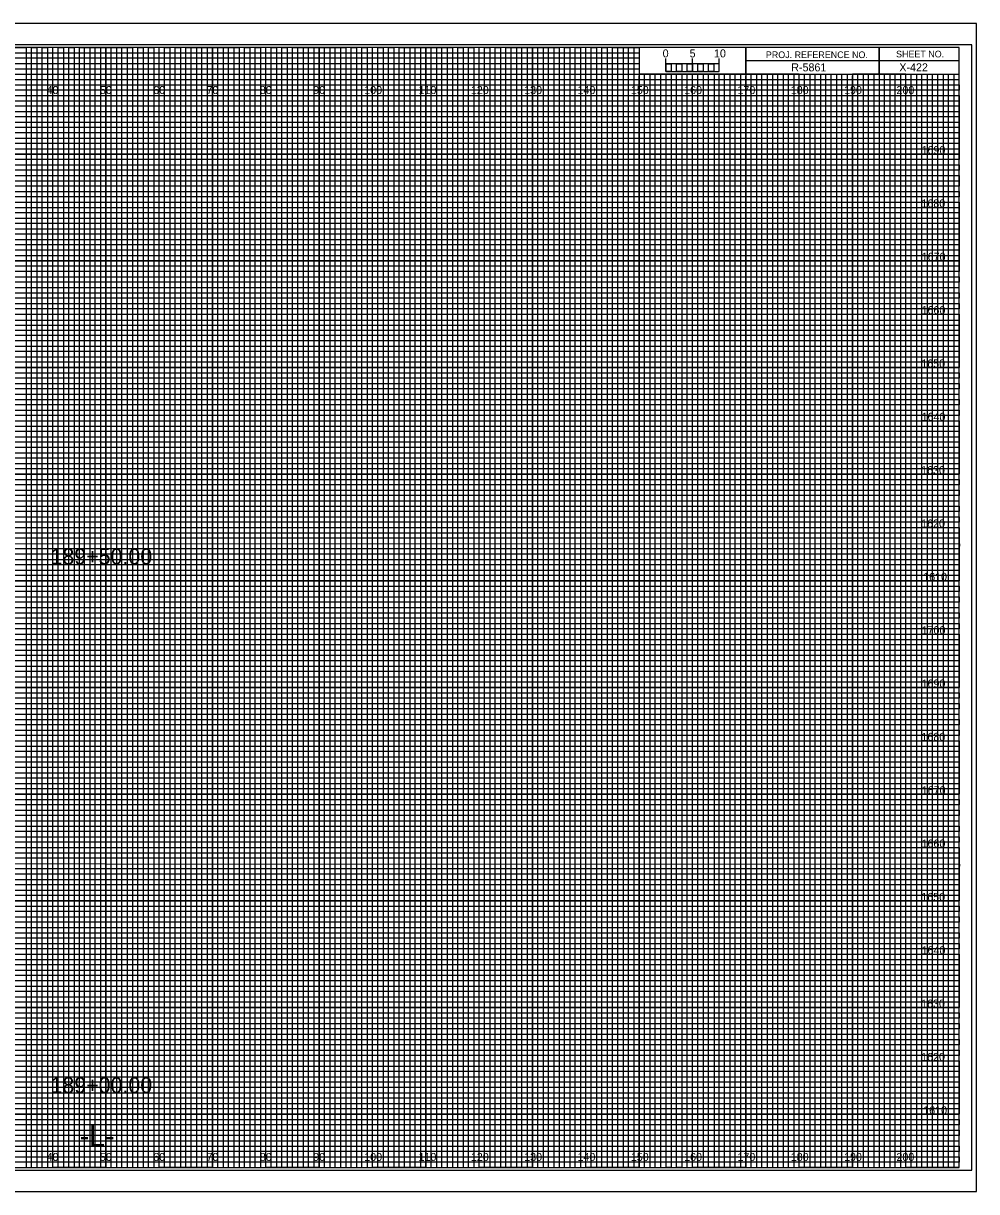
# Model space of a CAD drawing. Extents: x -13 to 323, y -5 to 6154.
# Drawn here: x 144.5 to 323.3, y 3955.5 to 4174.5 of the extents above; entities that cross this region are included whole.
import ezdxf

# ---------------------------------------------------------------- set-up
doc = ezdxf.new("R2010")
doc.units = 0
for name, color, linetype in [('Exist CMT Ground Line', 7, 'Continuous'), ('Prop Horizontal Alignment', 7, 'Continuous'), ('Prop Retaining Wall', 7, 'Continuous'), ('Prop XS Alignment Label', 7, 'Continuous'), ('Prop XS Bar Scale Labels', 7, 'Continuous'), ('Prop XS DDE', 7, 'Continuous'), ('Prop XS DDE Elevations', 7, 'Continuous'), ('Prop XS DDE Slope Text', 7, 'Continuous'), ('Prop XS Earthwork Shape', 7, 'Continuous'), ('Prop XS Elevation Labels', 7, 'Continuous'), ('Prop XS Project Number', 7, 'Continuous'), ('Prop XS Sheet Number', 7, 'Continuous'), ('Prop XS Station Labels', 7, 'Continuous'), ('Raster_Level_0', 7, 'Continuous'), ('Scratch_Level_3', 7, 'Continuous'), ('Sheet Cutting Line CELL', 7, 'Continuous')]:
    doc.layers.add(name, color=color, linetype=linetype)

msp = doc.modelspace()

# ---------------------------------------------------------------- linework, layer by layer
at = {"layer": 'Exist CMT Ground Line'}
for p, q in [((265, 4165.49), (265, 4167.9)), ((265, 4166.9), (265, 4167.9)), ((270, 4165.49), (270, 4167.9)), ((275, 4165.49), (275, 4167.9)), ((275, 4166.9), (275, 4167.9))]:
    msp.add_line(p, q, dxfattribs=at)
for points in [[(275, 4166.9), (265, 4166.9), (265, 4165.49), (275, 4165.49)], [(265, 4166.9), (266, 4166.9), (266, 4165.49), (265, 4165.49)], [(267, 4166.9), (268, 4166.9), (268, 4165.49), (267, 4165.49)], [(269, 4166.9), (270, 4166.9), (270, 4165.49), (269, 4165.49)], [(271, 4166.9), (272, 4166.9), (272, 4165.49), (271, 4165.49)], [(273, 4166.9), (274, 4166.9), (274, 4165.49), (273, 4165.49)]]:
    msp.add_lwpolyline(points, close=True, dxfattribs=at)
at = {"layer": 'Prop Retaining Wall'}
for p, q in [((0, 4169), (260, 4169)), ((260, 4167.98), (0, 4167.98)), ((260, 4169), (260, 4167.98)), ((0, 4167), (260, 4167)), ((260, 4165.89), (0, 4165.89)), ((260, 4167), (260, 4165.89)), ((0, 4164), (320, 4164))]:
    msp.add_line(p, q, dxfattribs=at)
for points in [[(0, 4163), (270, 4163), (320, 4163), (320, 4162), (0, 4162)], [(0, 4161), (320, 4161), (320, 4159), (0, 4159)], [(0, 4158), (320, 4158), (320, 4157), (0, 4156.98)], [(0, 4156), (320, 4156), (320, 4154), (0, 4154)], [(0, 4153), (320, 4153), (320, 4152), (0, 4152)], [(0, 4151), (320, 4151), (320, 4149), (0, 4149)], [(0, 4148), (320, 4148), (320, 4147), (0, 4147)], [(0, 4146), (320, 4146), (320, 4144), (0, 4144)], [(0, 4143), (320, 4143), (320, 4142), (0, 4142)], [(0, 4141), (320, 4141), (320, 4139), (0, 4139)], [(0, 4138), (320, 4138), (320, 4137), (0, 4137)], [(0, 4136), (320, 4136), (320, 4133.95), (320, 4133), (320, 4132), (0, 4132)], [(0, 4134), (320, 4134), (320, 4133), (0, 4133)], [(0, 4131), (320, 4131), (320, 4129), (0, 4129.03)], [(0, 4129.03), (320, 4129), (320, 4128), (0, 4128)], [(0, 4127), (320, 4127), (320, 4126), (0, 4126)], [(0, 4124), (320, 4124), (320, 4123), (0, 4123)], [(0, 4122), (320, 4122), (320, 4121), (0, 4121)], [(-0.07, 4118.89), (320, 4118.89), (320, 4117.88), (-0.07, 4117.88)], [(0, 4117), (320, 4117), (320, 4116), (0, 4116)], [(0, 4114), (320, 4114), (320, 4113), (0, 4113)], [(0, 4112), (320, 4112), (320, 4111), (0, 4111)], [(0, 4109), (320, 4109), (320, 4108), (0, 4108)], [(0, 4107), (320, 4107), (320, 4106), (0, 4106)], [(0, 4104), (320, 4104), (320, 4103), (0, 4103)], [(0, 4102), (320, 4102), (320, 4101), (0, 4101)], [(0, 4099), (320, 4099), (319.99, 4097.98), (0, 4098)], [(0, 4097), (320, 4097), (320, 4096), (0, 4096)], [(0, 4094), (320, 4094), (320, 4093), (0, 4093)], [(0, 4092), (320, 4092), (320, 4091), (0, 4091)], [(0, 4089), (320, 4089), (320, 4088), (0, 4088)], [(0, 4087), (320, 4087), (320, 4086), (0, 4086)], [(0, 4084), (320, 4084), (320, 4083), (0, 4083)], [(0, 4082), (320, 4082), (320, 4081), (0, 4081)], [(0, 4079), (320, 4079), (320, 4078), (0, 4078)], [(0, 4076.99), (320.07, 4076.91), (320, 4076), (0, 4076)], [(0, 4074), (320, 4074), (320, 4073), (0, 4073)], [(0, 4072), (320, 4072), (320, 4071), (0, 4071)], [(0, 4069), (320, 4069), (320, 4068), (0, 4068)], [(0, 4067), (320, 4067), (320, 4066), (0, 4066)], [(0, 4064), (320, 4064), (320, 4063), (0, 4063)], [(0, 4062), (320, 4062), (320, 4061), (0, 4061)], [(0, 4059), (320, 4059), (320, 4058), (0, 4058)], [(0, 4057), (320, 4057), (320, 4056), (0, 4056)], [(0, 4054), (320, 4054), (320, 4053), (0, 4053)], [(0, 4052), (320, 4052), (320, 4051), (0, 4051)], [(0, 4049), (320, 4049), (320, 4048), (0, 4048)], [(0, 4047), (320, 4047), (320, 4046), (0, 4046)], [(0, 4044), (320, 4044), (320, 4043), (0, 4043)], [(0, 4042), (320, 4042), (320, 4041), (0, 4041)], [(0, 4039), (320, 4039), (319.99, 4037.98), (0, 4038)], [(0, 4037), (320, 4037), (320, 4036), (0, 4036)], [(0, 4034), (320, 4034), (320, 4033), (0, 4033)], [(0, 4032), (320, 4032), (320, 4031), (0, 4031)], [(0, 4029), (320, 4029), (320, 4028), (0, 4028)], [(0, 4027), (320, 4027), (320, 4026), (0, 4026)], [(0, 4024), (320, 4024), (320, 4023), (0, 4023)], [(0, 4022), (320, 4022), (320, 4021), (0, 4021)], [(0, 4019), (320, 4019), (320, 4018), (0, 4018)], [(0, 4016.99), (320.07, 4016.91), (320, 4016), (0, 4016)], [(0, 4014), (320, 4014), (320, 4013), (0, 4013)], [(0, 4012), (320, 4012), (320, 4011), (0, 4011)], [(0, 4009), (320, 4009), (320, 4008), (0, 4008)], [(0, 4007), (320, 4007), (320, 4006), (0, 4006)], [(0, 4004), (320, 4004), (320, 4003), (0, 4003)], [(0, 4002), (320, 4002), (320, 4001), (0, 4001)], [(0, 3999), (320, 3999), (320, 3998), (0, 3998)], [(0, 3997), (320, 3997), (320, 3996), (0, 3996)], [(0, 3994), (320, 3994), (320, 3993), (0, 3993)], [(0, 3992), (320, 3992), (320, 3991), (0, 3991)], [(0, 3989), (320, 3989), (320, 3988), (0, 3988)], [(0, 3987), (320, 3987), (320, 3986), (0, 3986)], [(0, 3984), (320, 3984), (320, 3983), (0, 3983)], [(0, 3982), (320, 3982), (320, 3981), (0, 3981)], [(0, 3979), (320, 3979), (320, 3978), (0, 3978)], [(0, 3977), (320, 3977), (320, 3976), (0, 3976)], [(0, 3974), (320, 3974), (320, 3973), (0, 3973)], [(0, 3972), (320, 3972), (320, 3971), (0, 3971)], [(0, 3969), (320, 3969), (320, 3968), (0, 3968)], [(0, 3967), (320, 3967), (320, 3966), (0, 3966)], [(0, 3964), (320, 3964), (320, 3963), (0, 3963)], [(0, 3962), (320, 3962), (320, 3961), (0, 3961)]]:
    msp.add_lwpolyline(points, dxfattribs=at)
at = {"layer": 'Prop XS Alignment Label'}
for p, q in [((305, 4170), (305, 4165)), ((305, 4165), (305, 4170)), ((280, 4167.5), (280, 4165)), ((320, 4167.49), (280, 4167.49)), ((280, 4165), (320, 4165))]:
    msp.add_line(p, q, dxfattribs=at)
for points in [[(320, 4170), (0, 4170), (0, 3960), (320, 3960)], [(280, 4170), (260, 4170), (260, 4165.03), (280, 4165.03)], [(320, 4170), (280, 4170), (280, 4165), (320, 4165)]]:
    msp.add_lwpolyline(points, close=True, dxfattribs=at)
at = {"layer": 'Prop XS DDE'}
msp.add_lwpolyline([(-13.4, 3955.5), (323.3, 3955.5), (323.3, 4174.5), (-13.4, 4174.5)], close=True, dxfattribs=at)
at = {"layer": 'Prop XS DDE Elevations'}
for p, q in [((150, 3960), (150, 4170)), ((160, 3960), (160, 4170)), ((170, 3960), (170, 4170)), ((180, 3960), (180, 4170)), ((190, 3960), (190, 4170)), ((200, 3960), (200, 4170)), ((210, 3960), (210, 4170)), ((220, 3960), (220, 4170)), ((230, 3960), (230, 4170)), ((240, 3960), (240, 4170)), ((250, 3960), (250, 4170)), ((260, 3960), (260, 4164.69)), ((270, 3960), (270, 4164.69)), ((280, 3960), (280, 4164.69)), ((290, 3960), (290, 4164.69)), ((300, 3960), (300, 4164.69)), ((310, 3960), (310, 4164.69)), ((0, 4160), (320, 4160)), ((0, 4150), (320, 4150)), ((0, 4140), (320, 4140)), ((0, 4130), (320, 4130)), ((0, 4120), (320, 4120)), ((0, 4110), (320, 4110)), ((0, 4100), (320, 4100)), ((0, 4090), (320, 4090)), ((0, 4080), (320, 4080)), ((0, 4070), (320, 4070)), ((0, 4060), (320, 4060)), ((0, 4050), (320, 4050)), ((0, 4040), (320, 4040)), ((0, 4030), (320, 4030)), ((0, 4020), (320, 4020)), ((0, 4010), (320, 4010)), ((0, 4000), (320, 4000)), ((0, 3990), (320, 3990)), ((0, 3980), (320, 3980)), ((0, 3970), (320, 3970))]:
    msp.add_line(p, q, dxfattribs=at)
at = {"layer": 'Prop XS DDE Slope Text'}
msp.add_lwpolyline([(-10.8, 3959.5), (322.4, 3959.5), (322.4, 4170.5), (-10.8, 4170.5)], close=True, dxfattribs=at)
at = {"layer": 'Prop XS Earthwork Shape'}
for p, q in [((150, 4170), (140, 4170)), ((150, 3960), (150, 4170)), ((170, 4170), (160, 4170)), ((160, 4170), (160, 3960)), ((170, 3960), (170, 4170)), ((190, 4170), (180, 4170)), ((180, 4170), (180, 3960)), ((190, 3960), (190, 4170)), ((210, 4170), (200, 4170)), ((200, 4170), (200, 3960)), ((210, 3960), (210, 4170)), ((230, 4170), (220, 4170)), ((220, 4170), (220, 3960)), ((230, 3960), (230, 4170)), ((250, 4170), (240, 4170)), ((240, 4170), (240, 3960)), ((250, 3960), (250, 4170)), ((260, 4170), (260, 3960)), ((270, 3960), (270, 4165)), ((290, 4165), (280, 4165)), ((280, 4165), (280, 3960)), ((290, 3960), (290, 4165)), ((310, 4165), (300, 4165)), ((300, 4165), (300, 3960)), ((310, 3960), (310, 4165)), ((160, 3960), (150, 3960)), ((180, 3960), (170, 3960)), ((200, 3960), (190, 3960)), ((220, 3960), (210, 3960)), ((240, 3960), (230, 3960)), ((260, 3960), (250, 3960)), ((280, 3960), (270, 3960)), ((300, 3960), (290, 3960)), ((320, 3960), (310, 3960)), ((320, 3960), (320, 3960))]:
    msp.add_line(p, q, dxfattribs=at)
for points in [[(0, 4160), (320, 4160), (320, 4150), (0, 4150)], [(0, 4140), (320, 4140), (320, 4130), (0, 4130)], [(0, 4120), (320, 4120), (320, 4110), (0, 4110)], [(0, 4100), (320, 4100), (320, 4090), (0, 4090)], [(0, 4080), (320, 4080), (320, 4070), (0, 4070)], [(0, 4060), (320, 4060), (320, 4050), (0, 4050)], [(0, 4040), (320, 4040), (320, 4030), (0, 4030)], [(0, 4020), (320, 4020), (320, 4010), (0, 4010)], [(0, 4000), (320, 4000), (320, 3990), (0, 3990)], [(0, 3980), (320, 3980), (320, 3970), (0, 3970)]]:
    msp.add_lwpolyline(points, dxfattribs=at)
at = {"layer": 'Prop XS Elevation Labels'}
for p, q in [((267, 4165), (266.01, 4165)), ((266.01, 4165), (266.01, 3960)), ((267, 3960), (267, 4165)), ((269, 4165), (268, 4165)), ((268, 4165), (268, 3960)), ((269, 3960), (269, 4165)), ((266.01, 3960), (265, 3960)), ((268, 3960), (267, 3960))]:
    msp.add_line(p, q, dxfattribs=at)
for points in [[(145, 3960), (146, 3960), (146, 4170), (147, 4170), (147, 3960)], [(147, 3960), (148, 3960), (148, 4170), (149, 4170), (149, 3960)], [(150, 3960), (151, 3960), (151, 4170), (152, 4170), (152, 3960)], [(152, 3960), (153, 3960), (153, 4170), (154, 4170), (154, 3960)], [(155, 3960), (156, 3960), (156, 4170), (157, 4170), (157, 3960)], [(157, 3960), (158, 3960), (158, 4170), (159, 4170), (159, 3960)], [(160, 3960), (161, 3960), (161, 4170), (162, 4170), (162, 3960)], [(162, 3960), (163, 3960), (163, 4170), (164, 4170), (164, 3960)], [(165, 3960), (166, 3960), (166, 4170), (167, 4170), (167, 3960)], [(167, 3960), (168, 3960), (168, 4170), (169, 4170), (169, 3960)], [(170, 3960), (171, 3960), (171, 4170), (172, 4170), (172, 3960)], [(172, 3960), (173, 3960), (173, 4170), (174, 4170), (174, 3960)], [(175, 3960), (176, 3960), (176, 4170), (177, 4170), (177, 3960)], [(177, 3960), (178, 3960), (178, 4170), (179, 4170), (179, 3960)], [(180, 3960), (181, 3960), (181, 4170), (182, 4170), (182, 3960)], [(182, 3960), (183, 3960), (183, 4170), (184, 4170), (184, 3960)], [(185, 3960), (186, 3960), (186, 4170), (187, 4170), (187, 3960)], [(187, 3960), (188, 3960), (188, 4170), (189, 4170), (189, 3960)], [(190, 3960), (191, 3960), (191, 4170), (192, 4170), (192, 3960)], [(192, 3960), (193, 3960), (193, 4170), (194, 4170), (194, 3960)], [(195, 3960), (196, 3960), (196, 4170), (197, 4170), (197, 3960)], [(197, 3960), (198, 3960), (198, 4170), (199, 4170), (199, 3960)], [(200, 3960), (201, 3960), (201, 4170), (202, 4170), (202, 3960)], [(202, 3960), (203, 3960), (203, 4170), (204, 4170), (204, 3960)], [(205, 3960), (206, 3960), (206, 4170), (207, 4170), (207, 3960)], [(207, 3960), (208, 3960), (208, 4170), (209, 4170), (209, 3960)], [(210, 3960), (211, 3960), (211, 4170), (212, 4170), (212, 3960)], [(212, 3960), (213, 3960), (213, 4170), (214, 4170), (214, 3960)], [(215, 3960), (216, 3960), (216, 4170), (217, 4170), (217, 3960)], [(217, 3960), (218, 3960), (218, 4170), (219, 4170), (219, 3960)], [(220, 3960), (221, 3960), (221, 4170), (222, 4170), (222, 3960)], [(222, 3960), (223, 3960), (223, 4170), (224, 4170), (224, 3960)], [(225, 3960), (226, 3960), (226, 4170), (227, 4170), (227, 3960)], [(227, 3960), (228, 3960), (228, 4170), (229, 4170), (229, 3960)], [(230, 3960), (231, 3960), (231, 4170), (232, 4170), (232, 3960)], [(232, 3960), (233, 3960), (233, 4170), (234, 4170), (234, 3960)], [(235, 3960), (236, 3960), (236, 4170), (237, 4170), (237, 3960)], [(237, 3960), (238, 3960), (238, 4170), (239, 4170), (239, 3960)], [(240, 3960), (241, 3960), (241, 4170), (242, 4170), (242, 3960)], [(242, 3960), (243, 3960), (243, 4170), (244, 4170), (244, 3960)], [(245, 3960), (246, 3960), (246, 4170), (247, 4170), (247, 3960)], [(247, 3960), (248, 3960), (248, 4170), (249, 4170), (249, 3960)], [(250, 3960), (251, 3960), (251, 4170), (252, 4170), (252, 3960)], [(252, 3960), (253, 3960), (253, 4170), (254, 4170), (254, 3960)], [(255, 3960), (256, 3960), (256, 4170), (257, 4170), (257, 3960)], [(257, 3960), (258, 3960), (258, 4170), (259, 4170), (259, 3960)], [(260, 3960), (261, 3960), (261, 4165), (262.02, 4165), (262.02, 3960)], [(262, 3960), (263, 3960), (263, 4165), (263.99, 4165), (263.99, 3960)], [(270, 3960), (270.98, 3960), (270.98, 4165), (272, 4165), (272, 3960)], [(272, 3960), (273, 3960), (273, 4165), (274.05, 4165), (274.05, 3960)], [(275, 3960), (276, 3960), (276, 4165), (277, 4165), (277, 3960)], [(277, 3960), (278, 3960), (278, 4165), (279, 4165), (279, 3960)], [(280, 3960), (281, 3960), (281, 4165), (282, 4165), (282, 3960)], [(282, 3960), (283, 3960), (283, 4165), (284, 4165), (284, 3960)], [(285, 3960), (286, 3960), (286, 4165), (287, 4165), (287, 3960)], [(287, 3960), (288, 3960), (288, 4165), (289, 4165), (289, 3960)], [(290, 3960), (291, 3960), (291, 4165), (292, 4165), (292, 3960)], [(292, 3960), (293, 3960), (293, 4165), (294, 4165), (294, 3960)], [(295, 3960), (296, 3960), (296, 4165), (297, 4165), (297, 3960)], [(297, 3960), (298, 3960), (298, 4165), (299, 4165), (299, 3960)], [(300, 3960), (301, 3960), (301, 4165), (302, 4165), (302, 3960)], [(302, 3960), (303, 3960), (303, 4165), (304, 4165), (304, 3960)], [(305, 3960), (306, 3960), (306, 4165), (307, 4165), (307, 3960)], [(307, 3960), (308, 3960), (308, 4165), (309, 4165), (309, 3960)], [(310, 3960), (311, 3960), (311, 4165), (312, 4165), (312, 3960)], [(312, 3960), (313, 3960), (313, 4165), (314, 4165), (314, 3960)], [(315, 3960), (316, 3960), (316, 4165), (317, 4165), (317, 3960)], [(317, 3960), (318, 3960), (318, 4165), (319, 4165), (319, 3960)]]:
    msp.add_lwpolyline(points, dxfattribs=at)
at = {"layer": 'Prop XS Station Labels'}
for points in [[(135, 4170), (145, 4170), (145, 3960), (155, 3960), (155, 4170), (165, 4170), (165, 3960), (175, 3960), (175, 4170), (185, 4170), (185, 3960), (195, 3960), (195, 4170), (205, 4170), (205, 3960), (215, 3960), (215, 4170), (225, 4170), (225, 3960), (235, 3960), (235, 4170), (245, 4170), (245, 3960), (255, 3960), (255, 4170), (259.93, 4170), (260, 4170), (260, 4165), (264.99, 4165), (264.99, 3960), (275, 3960), (275, 4165), (285, 4165), (285, 3960), (295, 3960), (295, 4165), (305, 4165), (305, 3960), (315, 3960), (315, 4165)], [(0, 4165), (275, 4165)], [(0, 4145), (320, 4145), (320, 4155), (0, 4155)], [(0, 4125), (320, 4125), (320, 4135), (0, 4135)], [(0, 4105), (320, 4105), (320, 4115), (0, 4115)], [(0, 4085), (320, 4085), (320, 4095), (0, 4095)], [(0, 4065), (320, 4065), (320, 4075), (0, 4075)], [(0, 4045), (320, 4045), (320, 4055), (0, 4055)], [(0, 4025), (320, 4025), (320, 4035), (0, 4035)], [(0, 4005), (320, 4005), (320, 4015), (0, 4015)], [(0, 3985), (320, 3985), (320, 3995), (0, 3995)], [(0, 3965), (320, 3965), (320, 3975), (0, 3975)]]:
    msp.add_lwpolyline(points, dxfattribs=at)
at = {"layer": 'Sheet Cutting Line CELL'}
for p, q in [((323.3, 4174.5), (-13.4, 4174.5)), ((-13.4, 3955.5), (323.3, 3955.5))]:
    msp.add_line(p, q, dxfattribs=at)

# ---------------------------------------------------------------- texts
at = {"layer": 'Exist CMT Ground Line'}
msp.add_text('0', height=1.5, dxfattribs=at).set_placement((264.41, 4168.12))
at = {"layer": 'Prop Horizontal Alignment'}
for s, p in [('189+50.00', (149.59, 4073.08)), ('189+00.00', (149.59, 3973.96))]:
    msp.add_text(s, height=3, dxfattribs=at).set_placement(p)
at = {"layer": 'Prop XS Alignment Label'}
for s, height, p in [('PROJ. REFERENCE NO.', 1.25, (283.77, 4167.99)), ('SHEET NO.', 1.25, (308.19, 4168.12)), ('-L-', 4, (155.06, 3964))]:
    msp.add_text(s, height=height, dxfattribs=at).set_placement(p)
at = {"layer": 'Prop XS Bar Scale Labels'}
for s, p in [('5', (269.47, 4168.12)), ('10', (274.04, 4168.12))]:
    msp.add_text(s, height=1.5, dxfattribs=at).set_placement(p)
at = {"layer": 'Prop XS Project Number'}
msp.add_text('R-5861', height=1.5, dxfattribs=at).set_placement((288.53, 4165.5))
at = {"layer": 'Prop XS Sheet Number'}
msp.add_text('X-422', height=1.5, dxfattribs=at).set_placement((308.8, 4165.51))
at = {"layer": 'Raster_Level_0'}
for s, p in [('40', (148.86, 4161.25)), ('50', (158.86, 4161.25)), ('60', (168.86, 4161.25)), ('70', (178.86, 4161.25)), ('80', (188.86, 4161.25)), ('90', (198.86, 4161.25)), ('100', (208.44, 4161.25)), ('110', (218.62, 4161.25)), ('120', (228.44, 4161.25)), ('130', (238.44, 4161.25)), ('140', (248.44, 4161.25)), ('150', (258.44, 4161.25)), ('160', (268.44, 4161.25)), ('170', (278.44, 4161.25)), ('180', (288.44, 4161.25)), ('190', (298.44, 4161.25)), ('200', (308.26, 4161.25)), ('40', (148.86, 3961.25)), ('50', (158.86, 3961.25)), ('60', (168.86, 3961.25)), ('70', (178.86, 3961.25)), ('80', (188.86, 3961.25)), ('90', (198.86, 3961.25)), ('100', (208.44, 3961.25)), ('110', (218.62, 3961.25)), ('120', (228.44, 3961.25)), ('130', (238.44, 3961.25)), ('140', (248.44, 3961.25)), ('150', (258.44, 3961.25)), ('160', (268.44, 3961.25)), ('170', (278.44, 3961.25)), ('180', (288.44, 3961.25)), ('190', (298.44, 3961.25)), ('200', (308.26, 3961.25))]:
    msp.add_text(s, height=1.5, dxfattribs=at).set_placement(p)
at = {"layer": 'Scratch_Level_3'}
for s, p in [('1690', (312.97, 4150)), ('1680', (312.95, 4140)), ('1670', (313, 4130)), ('1660', (312.97, 4120)), ('1650', (312.92, 4110)), ('1640', (312.97, 4100)), ('1630', (312.89, 4090)), ('1620', (312.9, 4080)), ('1610', (313.28, 4070)), ('1700', (312.98, 4060)), ('1690', (312.97, 4050)), ('1680', (312.95, 4040)), ('1670', (313, 4030)), ('1660', (312.97, 4020)), ('1650', (312.92, 4010)), ('1640', (312.97, 4000)), ('1630', (312.89, 3990)), ('1620', (312.9, 3980)), ('1610', (313.28, 3970))]:
    msp.add_text(s, height=1.5, dxfattribs=at).set_placement(p)

doc.saveas('drawing.dxf')
